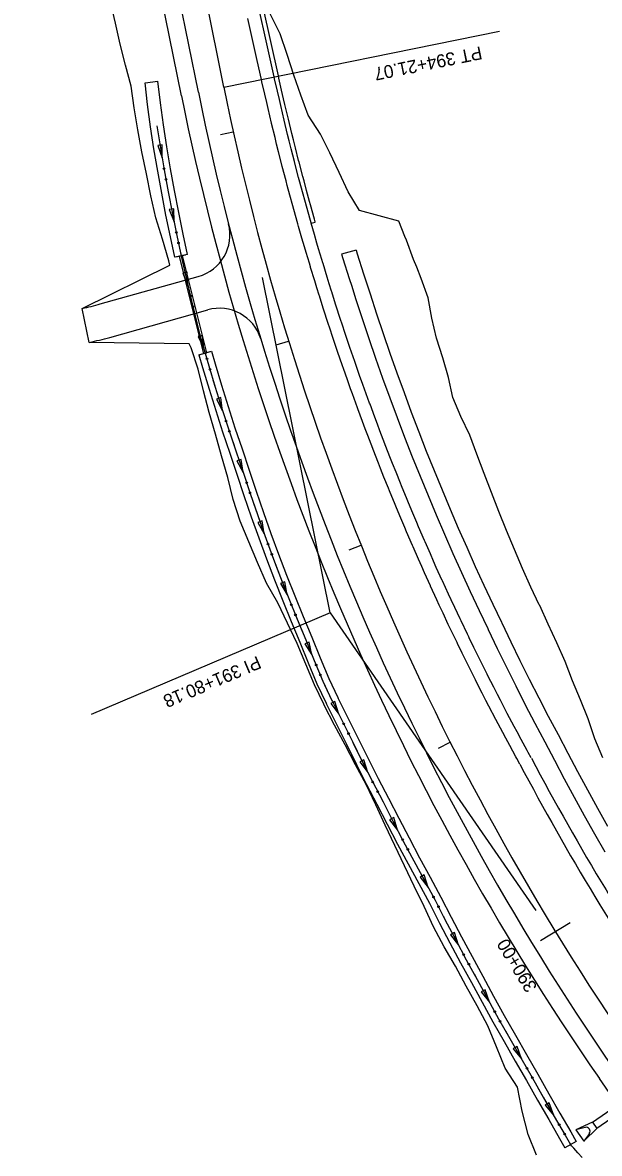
# Model space of a CAD drawing. Extents: x 948761 to 996004, y 1858548 to 1925175.
# Drawn here: x 960035 to 960302, y 1909705 to 1910227 of the extents above; entities that cross this region are included whole.
import ezdxf

# ---------------------------------------------------------------- set-up
doc = ezdxf.new("R2010")
doc.units = 0
for name, color, linetype in [('62', 7, 'Continuous'), ('R_Drainage', 7, 'Continuous'), ('R_Horz Alg', 7, 'Continuous'), ('R_Horz Alg Annot', 7, 'Continuous'), ('R_Proposed Const Limits', 7, 'Continuous'), ('R_Proposed Road', 7, 'Continuous')]:
    doc.layers.add(name, color=color, linetype=linetype)

msp = doc.modelspace()

# ---------------------------------------------------------------- linework, layer by layer
at = {"layer": '62'}
for p, q in [((960091.72, 1910199.37), (960097.68, 1910200.09)), ((960099.65, 1910170.81), (960097.56, 1910170.45)), ((960099.62, 1910164.71), (960099.65, 1910170.81)), ((960097.56, 1910170.45), (960099.62, 1910164.71)), ((960104.95, 1910141.27), (960102.87, 1910140.85)), ((960102.87, 1910140.85), (960105.11, 1910135.18)), ((960105.11, 1910135.18), (960104.95, 1910141.27)), ((960111.35, 1910120.12), (960105.49, 1910118.86)), ((960106.01, 1910118.97), (960110.36, 1910119.9)), ((960189.24, 1910122.11), (960182.5, 1910120.22)), ((960111.2, 1910111.92), (960109.14, 1910111.45)), ((960109.14, 1910111.45), (960111.49, 1910105.83)), ((960111.49, 1910105.83), (960111.2, 1910111.92)), ((960118.28, 1910082.78), (960116.24, 1910082.21)), ((960116.24, 1910082.21), (960118.87, 1910076.72)), ((960118.87, 1910076.72), (960118.28, 1910082.78)), ((960116.62, 1910073.74), (960122.39, 1910075.4)), ((960117.14, 1910073.89), (960121.87, 1910075.25)), ((960126.77, 1910054), (960124.75, 1910053.37)), ((960124.75, 1910053.37), (960127.54, 1910047.96)), ((960127.54, 1910047.96), (960126.77, 1910054)), ((960136.13, 1910025.49), (960134.12, 1910024.81)), ((960134.12, 1910024.81), (960137.05, 1910019.47)), ((960137.05, 1910019.47), (960136.13, 1910025.49)), ((960145.8, 1909997.07), (960143.8, 1909996.36)), ((960143.8, 1909996.36), (960146.81, 1909991.06)), ((960146.81, 1909991.06), (960145.8, 1909997.07)), ((960156.24, 1909968.94), (960154.27, 1909968.17)), ((960154.27, 1909968.17), (960157.44, 1909962.97)), ((960157.44, 1909962.97), (960156.24, 1909968.94)), ((960167.53, 1909941.13), (960165.57, 1909940.32)), ((960168.84, 1909935.18), (960167.53, 1909941.13)), ((960165.57, 1909940.32), (960168.84, 1909935.18)), ((960179.48, 1909913.66), (960177.59, 1909912.71)), ((960177.59, 1909912.71), (960181.24, 1909907.83)), ((960181.24, 1909907.83), (960179.48, 1909913.66)), ((960192.86, 1909886.77), (960190.98, 1909885.82)), ((960190.98, 1909885.82), (960194.63, 1909880.94)), ((960194.63, 1909880.94), (960192.86, 1909886.77)), ((960206.61, 1909860.08), (960204.73, 1909859.1)), ((960204.73, 1909859.1), (960208.44, 1909854.27)), ((960208.44, 1909854.27), (960206.61, 1909860.08)), ((960220.72, 1909833.58), (960218.85, 1909832.58)), ((960218.85, 1909832.58), (960222.61, 1909827.78)), ((960222.61, 1909827.78), (960220.72, 1909833.58)), ((960234.66, 1909806.96), (960232.79, 1909805.98)), ((960232.79, 1909805.98), (960236.51, 1909801.16)), ((960236.51, 1909801.16), (960234.66, 1909806.96)), ((960248.94, 1909780.55), (960247.08, 1909779.54)), ((960247.08, 1909779.54), (960250.85, 1909774.76)), ((960250.85, 1909774.76), (960248.94, 1909780.55)), ((960263.59, 1909754.36), (960261.76, 1909753.3)), ((960261.76, 1909753.3), (960265.67, 1909748.63)), ((960265.67, 1909748.63), (960263.59, 1909754.36)), ((960278.46, 1909728.26), (960276.63, 1909727.21)), ((960276.63, 1909727.21), (960280.55, 1909722.54)), ((960280.55, 1909722.54), (960278.46, 1909728.26)), ((960290.93, 1909710.54), (960285.73, 1909707.54))]:
    msp.add_line(p, q, dxfattribs=at)
for points in [[(960105.49, 1910118.86), (960103.48, 1910128.21), (960101.4, 1910138.35), (960099.45, 1910148.5), (960097.61, 1910158.67), (960095.86, 1910168.86), (960094.24, 1910179.09), (960092.93, 1910189.38), (960091.72, 1910199.37)], [(960111.35, 1910120.12), (960109.35, 1910129.44), (960107.29, 1910139.51), (960105.35, 1910149.6), (960103.52, 1910159.71), (960101.78, 1910169.84), (960100.18, 1910179.94), (960098.88, 1910190.11), (960097.68, 1910200.09)], [(960097.21, 1910179.52), (960097.21, 1910179.52), (960098.82, 1910169.35), (960100.57, 1910159.19), (960102.4, 1910149.05), (960104.35, 1910138.93), (960106.41, 1910128.83), (960108.58, 1910118.74), (960110.85, 1910108.68), (960112.74, 1910100.64), (960113.21, 1910098.64), (960115.66, 1910088.61), (960116.65, 1910084.68), (960116.65, 1910084.67), (960118.34, 1910078.64), (960121.19, 1910068.72), (960124.15, 1910058.83), (960127.22, 1910048.98), (960130.41, 1910039.16), (960133.69, 1910029.37), (960137.01, 1910019.6), (960140.26, 1910009.79), (960143.62, 1910000.03), (960147.08, 1909990.29), (960150.65, 1909980.59), (960154.32, 1909970.94), (960158.09, 1909961.31), (960161.97, 1909951.73), (960165.94, 1909942.19), (960169.89, 1909932.64), (960173.89, 1909923.1), (960178.04, 1909914.18), (960178.27, 1909913.73), (960182.91, 1909904.5), (960187.51, 1909895.24), (960192.08, 1909885.97), (960196.76, 1909876.75), (960201.52, 1909867.58), (960206.28, 1909858.41), (960211.05, 1909849.25), (960215.91, 1909840.12), (960220.87, 1909831.06), (960225.73, 1909821.94), (960230.45, 1909812.72), (960235.26, 1909803.55), (960240.16, 1909794.43), (960245.15, 1909785.35), (960250.07, 1909776.23), (960255.08, 1909767.14), (960260.2, 1909758.11), (960265.39, 1909749.12), (960270.53, 1909740.08), (960275.65, 1909731.01), (960280.82, 1909722.08), (960285.83, 1909713.39), (960288.33, 1909709.04)], [(960097.21, 1910179.52), (960097.21, 1910179.52), (960098.82, 1910169.35), (960099.62, 1910164.71)], [(960102.24, 1910149.95), (960102.25, 1910149.91)], [(960102.25, 1910149.91), (960102.4, 1910149.05), (960104.35, 1910138.93), (960105.11, 1910135.18)], [(960108.2, 1910120.51), (960108.21, 1910120.47)], [(960108.21, 1910120.47), (960108.58, 1910118.74), (960110.85, 1910108.68), (960111.52, 1910105.84)], [(960182.5, 1910120.22), (960183.12, 1910118.25), (960186.06, 1910109), (960187.23, 1910105.43), (960189.02, 1910099.79), (960192.03, 1910090.56), (960195.11, 1910081.36), (960198.26, 1910072.18), (960201.5, 1910063.03), (960204.8, 1910053.91), (960208.19, 1910044.82), (960211.64, 1910035.75), (960215.18, 1910026.72), (960218.78, 1910017.72), (960222.46, 1910008.75), (960226.22, 1909999.82), (960230.04, 1909990.91), (960233.94, 1909982.04), (960237.92, 1909973.21), (960241.96, 1909964.41), (960246.08, 1909955.64), (960250.05, 1909947.35), (960250.25, 1909946.94), (960254.41, 1909938.21), (960258.66, 1909929.5), (960262.98, 1909920.84), (960267.37, 1909912.21), (960271.83, 1909903.62), (960276.36, 1909895.09), (960280.85, 1909886.57), (960285.37, 1909878.02), (960289.96, 1909869.5), (960294.63, 1909861.02), (960299.37, 1909852.58), (960304.18, 1909844.18)], [(960189.24, 1910122.11), (960189.79, 1910120.35), (960192.73, 1910111.15), (960193.93, 1910107.44), (960193.94, 1910107.43), (960195.69, 1910101.93), (960198.67, 1910092.75), (960201.74, 1910083.6), (960204.87, 1910074.48), (960208.09, 1910065.39), (960211.38, 1910056.32), (960214.74, 1910047.28), (960218.17, 1910038.28), (960221.68, 1910029.3), (960225.27, 1910020.35), (960228.93, 1910011.44), (960232.66, 1910002.56), (960236.46, 1909993.71), (960240.34, 1909984.89), (960244.29, 1909976.1), (960248.31, 1909967.36), (960252.4, 1909958.64), (960256.37, 1909950.36), (960256.57, 1909949.94), (960260.72, 1909941.25), (960264.94, 1909932.6), (960269.23, 1909923.99), (960273.59, 1909915.41), (960278.03, 1909906.88), (960282.55, 1909898.37), (960287.04, 1909889.83), (960291.54, 1909881.32), (960296.11, 1909872.85), (960300.75, 1909864.42), (960305.46, 1909856.03)], [(960115.02, 1910091.25), (960115.03, 1910091.22)], [(960115.03, 1910091.22), (960115.66, 1910088.61), (960116.65, 1910084.68), (960116.65, 1910084.67), (960118.34, 1910078.64), (960118.89, 1910076.72)], [(960116.62, 1910073.74), (960118.31, 1910067.87), (960121.28, 1910057.96), (960124.37, 1910048.07), (960127.56, 1910038.22), (960130.85, 1910028.41), (960134.17, 1910018.64), (960137.42, 1910008.83), (960140.79, 1909999.03), (960144.26, 1909989.27), (960147.84, 1909979.54), (960151.52, 1909969.85), (960155.31, 1909960.2), (960159.19, 1909950.59), (960163.17, 1909941.04), (960167.12, 1909931.48), (960171.15, 1909921.89), (960175.34, 1909912.88), (960175.58, 1909912.39), (960180.23, 1909903.15), (960184.82, 1909893.91), (960189.4, 1909884.63), (960194.09, 1909875.38), (960198.86, 1909866.2), (960203.62, 1909857.03), (960208.4, 1909847.85), (960213.27, 1909838.7), (960218.23, 1909829.63), (960223.08, 1909820.55), (960227.78, 1909811.34), (960232.61, 1909802.15), (960237.52, 1909793), (960242.51, 1909783.92), (960247.43, 1909774.79), (960252.46, 1909765.67), (960257.6, 1909756.63), (960262.79, 1909747.63), (960267.92, 1909738.6), (960273.05, 1909729.53), (960278.22, 1909720.58), (960283.23, 1909711.89), (960285.73, 1909707.54)], [(960122.39, 1910075.4), (960124.07, 1910069.57), (960127.02, 1910059.71), (960130.08, 1910049.89), (960133.26, 1910040.1), (960136.53, 1910030.33), (960139.85, 1910020.55), (960143.1, 1910010.75), (960146.45, 1910001.02), (960149.9, 1909991.31), (960153.46, 1909981.65), (960157.12, 1909972.02), (960160.88, 1909962.42), (960164.74, 1909952.87), (960168.71, 1909943.34), (960172.65, 1909933.79), (960176.63, 1909924.32), (960180.75, 1909915.48), (960180.95, 1909915.08), (960185.6, 1909905.84), (960190.2, 1909896.57), (960194.77, 1909887.31), (960199.43, 1909878.12), (960204.19, 1909868.96), (960208.94, 1909859.79), (960213.71, 1909850.64), (960218.55, 1909841.55), (960223.51, 1909832.48), (960228.39, 1909823.33), (960233.11, 1909814.1), (960237.9, 1909804.96), (960242.79, 1909795.86), (960247.78, 1909786.79), (960252.7, 1909777.66), (960257.7, 1909768.61), (960262.81, 1909759.6), (960267.99, 1909750.61), (960273.14, 1909741.56), (960278.26, 1909732.5), (960283.41, 1909723.58), (960288.42, 1909714.88), (960290.93, 1909710.54)], [(960123.1, 1910062.33), (960123.11, 1910062.29)], [(960123.11, 1910062.29), (960124.15, 1910058.83), (960127.22, 1910048.98), (960127.55, 1910047.96)], [(960132.23, 1910033.71), (960132.25, 1910033.68)], [(960132.25, 1910033.68), (960133.69, 1910029.37), (960137.01, 1910019.6), (960137.05, 1910019.47)], [(960141.82, 1910005.25), (960141.84, 1910005.21)], [(960141.84, 1910005.21), (960143.62, 1910000.03), (960146.81, 1909991.06)], [(960152.02, 1909976.99), (960152.03, 1909976.96)], [(960152.03, 1909976.96), (960154.32, 1909970.94), (960157.44, 1909962.97)], [(960163.08, 1909949.07), (960163.09, 1909949.03)], [(960163.09, 1909949.03), (960165.94, 1909942.19), (960168.84, 1909935.18)], [(960174.7, 1909921.37), (960174.71, 1909921.33)], [(960174.71, 1909921.33), (960178.04, 1909914.18), (960178.27, 1909913.73), (960181.24, 1909907.83)], [(960187.92, 1909894.4), (960187.94, 1909894.37)], [(960187.94, 1909894.37), (960192.08, 1909885.97), (960194.63, 1909880.94)], [(960201.51, 1909867.61), (960201.52, 1909867.58), (960201.53, 1909867.58)], [(960201.53, 1909867.58), (960206.28, 1909858.41), (960208.44, 1909854.27)], [(960215.44, 1909841), (960215.46, 1909840.97)], [(960215.46, 1909840.97), (960215.91, 1909840.12), (960220.87, 1909831.06), (960222.61, 1909827.78)], [(960229.55, 1909814.48), (960229.56, 1909814.45)], [(960229.56, 1909814.45), (960230.45, 1909812.72), (960235.26, 1909803.55), (960236.54, 1909801.17)], [(960243.7, 1909787.99), (960243.72, 1909787.96)], [(960243.72, 1909787.96), (960245.15, 1909785.35), (960250.07, 1909776.23), (960250.87, 1909774.77)], [(960258.18, 1909761.67), (960258.2, 1909761.64)], [(960258.2, 1909761.64), (960260.2, 1909758.11), (960265.39, 1909749.12), (960265.67, 1909748.63)], [(960273.07, 1909735.59), (960273.09, 1909735.55)], [(960273.09, 1909735.55), (960275.65, 1909731.01), (960280.55, 1909722.54)], [(960288.04, 1909709.55), (960288.06, 1909709.51)], [(960288.06, 1909709.51), (960288.33, 1909709.04)], [(960293.7, 1909703.02), (960291.7, 1909705.29), (960289.79, 1909707.43), (960289.53, 1909707.73), (960288.79, 1909708.54), (960288.33, 1909709.04)], [(960291.96, 1909704.99), (960291.7, 1909705.29), (960289.79, 1909707.43), (960289.53, 1909707.73), (960288.79, 1909708.54), (960288.33, 1909709.04)]]:
    msp.add_lwpolyline(points, dxfattribs=at)
for centre in [(960100.5, 1910159.79), (960101.39, 1910154.86), (960106.15, 1910130.29), (960107.19, 1910125.39), (960112.7, 1910100.97), (960113.87, 1910096.1), (960120.31, 1910071.92), (960121.71, 1910067.11), (960129.13, 1910043.21), (960130.68, 1910038.45), (960138.66, 1910014.73), (960140.24, 1910009.97), (960148.57, 1909986.37), (960150.3, 1909981.67), (960159.34, 1909958.33), (960161.22, 1909953.69), (960170.79, 1909930.57), (960172.73, 1909925.95), (960183.51, 1909903.37), (960185.74, 1909898.88), (960196.93, 1909876.5), (960199.24, 1909872.05), (960210.78, 1909849.84), (960213.13, 1909845.42), (960225, 1909823.39), (960227.31, 1909818.94), (960238.94, 1909796.78), (960241.33, 1909792.37), (960253.32, 1909770.41), (960255.75, 1909766.03), (960268.17, 1909744.3), (960270.65, 1909739.94), (960283.08, 1909718.22), (960285.58, 1909713.88)]:
    msp.add_circle(centre, 0.375, dxfattribs=at)
at = {"layer": 'R_Drainage'}
for p, q in [((960108.98, 1910119.62), (960107.53, 1910119.25)), ((960107.53, 1910119.25), (960118.75, 1910074.39)), ((960120.2, 1910074.76), (960108.98, 1910119.62)), ((960118.75, 1910074.39), (960120.2, 1910074.76)), ((960298.4, 1909719.34), (960358.62, 1909760.97)), ((960360.61, 1909758.09), (960300.39, 1909716.46)), ((960298.4, 1909719.34), (960290.83, 1909715.93)), ((960295.05, 1909716.97), (960290.83, 1909715.93)), ((960300.39, 1909716.46), (960294.52, 1909710.58)), ((960298.4, 1909719.34), (960300.39, 1909716.46)), ((960290.83, 1909715.93), (960294.52, 1909710.58)), ((960297, 1909714.15), (960294.52, 1909710.58))]:
    msp.add_line(p, q, dxfattribs=at)
msp.add_arc((960295.49, 1909715.2), 1.83, 325.3114, 103.9331, dxfattribs=at)
at = {"layer": 'R_Horz Alg'}
msp.add_line((960128.14, 1910197.39), (960035.16, 1910656.78), dxfattribs=at)
msp.add_arc((961310.39, 1910436.68), 1206.23, 191.44192, 214.64982, dxfattribs=at)
at = {"layer": 'R_Horz Alg Annot'}
for q in [(960145.93, 1910109.45), (960272.29, 1909817.14)]:
    msp.add_line((960177.27, 1909954.63), q, dxfattribs=at)
for points in [[(960128.14, 1910197.39), (960255.55, 1910223.18)], [(960126.64, 1910175.48), (960132.5, 1910176.78)], [(960152.33, 1910078.36), (960158.06, 1910080.13)], [(960185.98, 1909983.69), (960191.55, 1909985.93)], [(960177.27, 1909954.63), (960066.85, 1909907.65)], [(960227.35, 1909892.14), (960232.71, 1909894.83)], [(960274.46, 1909803.28), (960288.11, 1909811.62)]]:
    msp.add_lwpolyline(points, dxfattribs=at)
at = {"layer": 'R_Proposed Const Limits'}
for points in [[(960088.46, 1910177.66), (960086.77, 1910187.89), (960085.33, 1910197.84), (960082.68, 1910207.5), (960080.16, 1910217.2), (960078.08, 1910226.98), (960075.83, 1910236.73)], [(960167.1, 1910184.41), (960163.72, 1910193.62), (960160.48, 1910202.88), (960157.44, 1910212.43), (960154.13, 1910221.96), (960149.46, 1910231.22)], [(960208.92, 1910135.5), (960190.87, 1910140.51), (960185.59, 1910149.07), (960181.43, 1910157.96), (960177.14, 1910167.11), (960172.73, 1910175.74), (960167.1, 1910184.41)], [(960062.66, 1910095.19), (960103.15, 1910115.22), (960102.7, 1910117.19), (960099.74, 1910127.12), (960096.69, 1910137.04), (960094.42, 1910147.15), (960092.37, 1910157.31), (960090.31, 1910167.47), (960088.46, 1910177.66)], [(960303.18, 1909887.69), (960299.49, 1909896.5), (960296.45, 1909905.64), (960292.84, 1909914.45), (960289.21, 1909923.24), (960285.79, 1909932.11), (960281.97, 1909940.78), (960278.02, 1909949.38), (960274.06, 1909957.98), (960273.87, 1909958.39), (960269.9, 1909966.49), (960266.1, 1909975.16), (960262.49, 1909983.91), (960258.78, 1909992.61), (960255.23, 1910001.39), (960251.73, 1910010.18), (960248.34, 1910019.01), (960245.03, 1910027.88), (960241.71, 1910036.74), (960237.64, 1910045.32), (960233.99, 1910054.07), (960231.89, 1910063.36), (960229.26, 1910072.46), (960226.34, 1910081.46), (960224.21, 1910090.71), (960222.54, 1910100.08), (960219.35, 1910108.98), (960217.23, 1910114.33), (960217.22, 1910114.33), (960215.79, 1910117.78), (960212.48, 1910126.67), (960211.76, 1910128.43), (960208.92, 1910135.5)], [(960272.54, 1909704.2), (960268.76, 1909713.75), (960265.99, 1909724.43), (960263.88, 1909735.63), (960258.17, 1909744.37), (960254.07, 1909754.16), (960250.07, 1909763.96), (960245.12, 1909773.14), (960240.02, 1909782.22), (960235.16, 1909791.43), (960229.89, 1909800.4), (960225.03, 1909809.59), (960220.68, 1909819.07), (960216.12, 1909828.42), (960211.56, 1909837.75), (960207.1, 1909847.14), (960202.73, 1909856.55), (960198.38, 1909865.97), (960193.86, 1909875.3), (960188.92, 1909884.41), (960184.15, 1909893.62), (960179.33, 1909902.8), (960174.49, 1909911.99), (960174.26, 1909912.43), (960169.95, 1909921.32), (960166.02, 1909930.93), (960161.99, 1909940.49), (960157.6, 1909949.89), (960153.06, 1909959.24), (960147.9, 1909968.35), (960143.71, 1909977.86), (960139.67, 1909987.45), (960135.61, 1909997.03), (960132.45, 1910006.94), (960130.04, 1910017.12), (960127.11, 1910027.09), (960124.23, 1910037.08), (960121.42, 1910047.07), (960118.76, 1910057.11), (960116.27, 1910067.2), (960112.98, 1910077.03), (960112.14, 1910078.86), (960065.98, 1910079.54)]]:
    msp.add_lwpolyline(points, dxfattribs=at)
at = {"layer": 'R_Proposed Road'}
for p, q in [((960108.53, 1910193.43), (960046.05, 1910502.16)), ((960116.37, 1910195.01), (960053.89, 1910503.75)), ((960168.47, 1910134.59), (960170.4, 1910135.1)), ((960071.06, 1910097.26), (960116.34, 1910109.96)), ((960065.98, 1910079.54), (960062.66, 1910095.19)), ((960075.38, 1910081.85), (960120.67, 1910094.56)), ((960542.71, 1909390.69), (960301.64, 1909739.5))]:
    msp.add_line(p, q, dxfattribs=at)
for points in [[(960168.47, 1910134.59), (960168.43, 1910134.7), (960168.1, 1910135.89), (960166.25, 1910142.48), (960165.8, 1910144.12), (960164.44, 1910149.07), (960163.23, 1910153.58), (960162.68, 1910155.67), (960160.94, 1910162.3), (960160.75, 1910163.05), (960159.25, 1910168.93), (960158.34, 1910172.56), (960157.6, 1910175.56), (960156.01, 1910182.09), (960155.99, 1910182.2), (960154.41, 1910188.87), (960153.77, 1910191.62), (960152.87, 1910195.53), (960151.6, 1910201.19), (960151.37, 1910202.21), (960140.79, 1910249.98)], [(960170.4, 1910135.1), (960170.36, 1910135.25), (960170.02, 1910136.43), (960168.18, 1910143.02), (960167.73, 1910144.65), (960166.37, 1910149.6), (960165.17, 1910154.1), (960164.61, 1910156.18), (960162.88, 1910162.8), (960162.69, 1910163.55), (960161.19, 1910169.42), (960160.28, 1910173.04), (960159.54, 1910176.03), (960157.96, 1910182.56), (960157.93, 1910182.66), (960156.35, 1910189.33), (960155.72, 1910192.07), (960154.82, 1910195.97), (960153.55, 1910201.62), (960153.32, 1910202.64), (960142.74, 1910250.42)], [(960264.88, 1909884.75), (960263.48, 1909887.33), (960263.04, 1909888.14), (960260.21, 1909893.34), (960258.37, 1909896.76), (960256.97, 1909899.37), (960253.77, 1909905.42), (960253.77, 1909905.42), (960250.6, 1909911.49), (960249.24, 1909914.11), (960247.46, 1909917.57), (960244.78, 1909922.85), (960244.36, 1909923.68), (960241.3, 1909929.8), (960240.39, 1909931.62), (960238.27, 1909935.94), (960236.08, 1909940.44), (960235.87, 1909940.86), (960235.27, 1909942.1), (960232.31, 1909948.28), (960231.83, 1909949.28), (960229.39, 1909954.47), (960227.66, 1909958.17), (960226.5, 1909960.68), (960223.65, 1909966.91), (960223.57, 1909967.09), (960220.83, 1909973.16), (960219.54, 1909976.04), (960218.05, 1909979.42), (960215.59, 1909985.04), (960215.3, 1909985.7), (960212.59, 1909992), (960211.72, 1909994.06), (960209.92, 1909998.31), (960207.92, 1910003.11), (960207.29, 1910004.64), (960204.69, 1910010.98), (960204.19, 1910012.21), (960202.12, 1910017.34), (960200.54, 1910021.33), (960199.59, 1910023.72), (960197.1, 1910030.11), (960196.96, 1910030.48), (960194.65, 1910036.52), (960193.46, 1910039.66), (960192.23, 1910042.94), (960190.04, 1910048.88), (960189.86, 1910049.37), (960187.51, 1910055.82), (960186.69, 1910058.12), (960185.21, 1910062.29), (960183.42, 1910067.39), (960182.94, 1910068.77), (960180.71, 1910075.26), (960180.22, 1910076.69), (960178.52, 1910081.76), (960177.1, 1910086.02), (960176.36, 1910088.28), (960174.24, 1910094.81), (960174.06, 1910095.38), (960172.25, 1910101.07), (960172.25, 1910101.07), (960172.16, 1910101.35), (960171.09, 1910104.76), (960170.12, 1910107.91), (960168.21, 1910114.16), (960168.11, 1910114.48), (960167.64, 1910116.05), (960166.14, 1910121.06), (960165.4, 1910123.6), (960164.21, 1910127.66), (960162.67, 1910133.05), (960162.32, 1910134.26), (960160.47, 1910140.88), (960160.01, 1910142.53), (960158.65, 1910147.51), (960157.44, 1910152.04), (960156.88, 1910154.14), (960155.14, 1910160.79), (960154.94, 1910161.56), (960153.44, 1910167.46), (960152.52, 1910171.11), (960151.77, 1910174.13), (960150.18, 1910180.68), (960150.15, 1910180.81), (960148.57, 1910187.5), (960147.92, 1910190.27), (960147.02, 1910194.2), (960145.74, 1910199.88), (960145.51, 1910200.91), (960143.58, 1910209.63), (960141.42, 1910219.39), (960139.26, 1910229.16)], [(960270.16, 1909887.6), (960268.76, 1909890.2), (960268.31, 1909891.01), (960265.49, 1909896.2), (960263.66, 1909899.6), (960262.27, 1909902.19), (960259.08, 1909908.2), (960255.92, 1909914.25), (960254.57, 1909916.86), (960252.8, 1909920.3), (960250.13, 1909925.56), (960249.72, 1909926.37), (960246.67, 1909932.47), (960245.77, 1909934.28), (960243.65, 1909938.58), (960241.47, 1909943.06), (960241.27, 1909943.48), (960240.68, 1909944.7), (960237.73, 1909950.86), (960237.26, 1909951.85), (960234.82, 1909957.02), (960233.1, 1909960.7), (960231.95, 1909963.19), (960229.1, 1909969.4), (960229.03, 1909969.56), (960226.3, 1909975.61), (960225.03, 1909978.48), (960223.54, 1909981.84), (960221.09, 1909987.43), (960220.81, 1909988.08), (960218.11, 1909994.36), (960217.24, 1909996.4), (960215.45, 1910000.63), (960213.46, 1910005.42), (960212.83, 1910006.92), (960210.24, 1910013.25), (960209.75, 1910014.45), (960207.69, 1910019.57), (960206.12, 1910023.53), (960205.18, 1910025.91), (960202.7, 1910032.28), (960202.56, 1910032.63), (960200.26, 1910038.65), (960199.08, 1910041.78), (960197.86, 1910045.03), (960195.67, 1910050.95), (960195.49, 1910051.43), (960193.16, 1910057.86), (960192.34, 1910060.14), (960190.87, 1910064.28), (960189.08, 1910069.37), (960188.61, 1910070.72), (960186.39, 1910077.2), (960185.9, 1910078.61), (960184.21, 1910083.66), (960182.8, 1910087.9), (960182.06, 1910090.14), (960179.95, 1910096.65), (960179.78, 1910097.2), (960177.97, 1910102.88), (960177.89, 1910103.15), (960176.82, 1910106.54), (960175.85, 1910109.68), (960173.95, 1910115.91), (960173.85, 1910116.22), (960173.38, 1910117.77), (960171.9, 1910122.77), (960171.16, 1910125.28), (960169.98, 1910129.32), (960168.47, 1910134.59)]]:
    msp.add_lwpolyline(points, dxfattribs=at)
for centre, radius, start, end in [((961310.39, 1910436.68), 1226.23, 191.44192, 214.64982), ((961310.39, 1910436.68), 1218.23, 191.44192, 214.64982), ((960110.94, 1910129.22), 20, 285.6729, 14.3772), ((960034.86, 1910226.28), 134, 281.9743, 285.6729), ((960126.07, 1910075.3), 20, 16.9687, 105.6729), ((960034.86, 1910226.28), 150, 281.9743, 285.6729), ((961310.39, 1910436.68), 1182.23, 207.82961, 214.64982), ((961310.39, 1910436.68), 1176.23, 207.82961, 214.64982)]:
    msp.add_arc(centre, radius, start, end, dxfattribs=at)

# ---------------------------------------------------------------- texts
at = {"layer": 'R_Horz Alg'}
msp.add_text('+', height=1, rotation=101.4419, dxfattribs=at).set_placement((960128.63, 1910197.49))
at = {"layer": 'R_Horz Alg Annot'}
for s, rotation, p in [('PT 394+21.07', 191.4419, (960246.74, 1910216.3)), ('PI 391+80.18', 203.0459, (960143.66, 1909934.89)), ('390+00', 121.4429, (960273.12, 1909781.78))]:
    msp.add_text(s, height=6, rotation=rotation, dxfattribs=at).set_placement(p)

doc.saveas('drawing.dxf')
